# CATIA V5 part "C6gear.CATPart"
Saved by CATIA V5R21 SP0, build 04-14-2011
Part number: C6gear
Bounding box of the stored display mesh (mm): x 0 to 31.75, y -37.949 to 37.949, z -37.949 to 37.949
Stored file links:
  C:\Users\User\Desktop\B.D.M.A\Chapter6\C6gear.CATPart
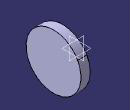
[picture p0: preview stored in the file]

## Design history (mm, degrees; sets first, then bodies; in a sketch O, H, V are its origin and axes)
Body1 (main body)
  Sketch1 on xy-plane, origin (0, 0, 0), H (1, 0, 0), V (0, 1, 0)
    line L1 (0, 0) -> (31.75, 0)
    line L2 (31.75, 0) -> (31.75, 38.1)
    line L3 (31.75, 38.1) -> (19.05, 38.1)
    line L4 (19.05, 38.1) -> (19.05, 6.35)
    line L5 (19.05, 6.35) -> (0, 6.35)
    point P5 (0, 6.35)
    line L6 (0, 6.35) -> (0, 0)
    length L2 = 38.1
    length L6 = 6.35
    length L5 = 19.05
    length L3 = 12.7
    horizontal: L1 H, L3 H, L5 H
    vertical: L2 V, L4 V, L6 V
    coincidence: P5 V
  Shaft1: profile Sketch1, axis Sketch1.L1, angle 360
